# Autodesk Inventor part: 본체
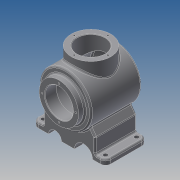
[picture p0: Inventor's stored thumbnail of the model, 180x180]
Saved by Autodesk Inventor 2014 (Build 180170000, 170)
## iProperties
Created: 2018-08
Part Number: 본체
Material: Generic
Document SubType Name: Modeling
Designer: kb542
Density: 1 g/cm^3
Appearance: Default
Author: kb542
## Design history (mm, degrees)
sketch "스케치1"
  geometry: L1 (-60, 0)-(60, 0); L2 (-60, 27)-(-60, 38); L3 (-60, 38)-(-48, 38); L4 (-48, 38)-(-48, 50); L5 (-60, 27)-(-38, 27); L6 (-38, 27)-(-38, 40); L7 (-38, 40)-(42.163, 40); L8 (-48, 50)-(48.671, 50); A1 r 116 centre (-56, 0) between (60, 0) and (48.671, 50); A2 r 106 centre (-56, 0) between (50, 0) and (42.163, 40); 2 further points
  constraints: 16 end point, 4 perpendicular, 4 point on circle, 2 centre point, 2 parallel, 1 coincident, 1 concentric, 1 horizontal, 1 horizontal alignment, 1 midpoint, 1 point on line, 1 vertical alignment
  dimensions: "d0" = 10 radial gap between concentric circles of A1 A2; "d2" = 12 distance of L2.end L3.end; "d4" = 54 diameter of L5 L1; "d5" = 76 diameter of L3 L1; "d6" = 80 diameter of L7 L1; "d7" = 100 diameter of L8 L1; "d8" = 116 radius of A1; "d9" = 22 distance of L2.start L5.end; "d10" = 108 distance from line of L1.end L4
revolve "회전1" sketch "스케치1" stored, may be unused: angle "d11" = 90 deg
node "작업 평면1"
sketch "스케치3"
  geometry: L1 (-50, -43.437)-(-50, -72); L2 (-50, -72)-(-70, -72); L3 (-70, -72)-(-70, -82); L4 (0, 0)-(0, -82); L5 (-70, -82)-(0, -82); L6 (70, -82)-(0, -82); L7 (50, -72)-(70, -72); L8 (70, -72)-(70, -82); L9 (-70, -72)-(-50, -43.437); L10 (70, -72)-(50, -43.437); L11 (50, -43.437)-(50, -72); L12 (-50, -43.437)-(-40.304, -29.59); L13 (50, -43.437)-(40.304, -29.59); C1 r 17.5 at (27.5, -82); C2 r 12.5 at (-27.5, -82); A1 r 50 centre (0, 0) between (-40.304, -29.59) and (40.304, -29.59); 1 further point
  constraints: 26 end point, 5 symmetric about line, 3 centre point, 3 perpendicular, 2 point on circle, 2 point on line, 1 parallel, 1 vertical, 3 other
  dimensions: "d14" = 20 distance between parallel lines of L3 L1; "d15" = 35 diameter of C1; "d16" = 25 diameter of C2; "d17" = 27.5 distance of C2.centre L4.end; "d18" = 27.5 distance of C1.centre L4.end; "d19" = 82 distance from line of L6 point (0, 0); "d21" = 10 distance between parallel lines of L6 L7; "d22" = 140 distance between parallel lines of L8 L3; "d25" = 35 deg angle of L3 L12; "d26" = 35 deg angle of L3 L9
extrude "돌출1" join sketch "스케치3" distance "d27" = 80; taper "d28" = 0 deg
extrude "돌출2" cut sketch "스케치3" stored distance "d29" = 80; taper "d30" = 0 deg
node "작업 평면2"
sketch "스케치4"
  geometry: L1 (-100, 32)-(-100, 108) reference; C1 r 38 at (-38, 70); 1 further point
  constraints: 1 centre point, 1 horizontal alignment
  dimensions: "d32" = 62 distance from line of C1.centre L1; "d33" = 76 diameter of C1
extrude "돌출3" join sketch "스케치4" stored distance "d34" = 80; taper "d35" = 0 deg
sketch "스케치5"
  geometry: C1 r 38 at (0, 0) reference; C2 r 27 at (0, 0); 1 further point
  constraints: 1 centre point, 1 coincident
  dimensions: "d36" = 54 diameter of C2
extrude "돌출4" cut sketch "스케치5" stored distance "d37" = 80; taper "d38" = 0 deg
sketch "스케치6"
  geometry: C1 r 27 at (0, 0) reference; 2 further points
  constraints: 1 horizontal alignment
  dimensions: "d39" = 32.5 distance of C1.centre point (-32.5, 0)
hole "구멍1" sketch "스케치6" at (-32.5, 0) diameter "d40" = 3.242; stored, may be unused: countersink angle "d44" = 90 deg, drill point angle "d46" = 118 deg; dims "d41" = 8, "d42" = 4, "d43" = 2, "d45" = 10
sketch "스케치7"
  geometry: C1 r 38 at (0, 0) reference; 1 further point
  constraints: 1 vertical alignment
  dimensions: "d50" = 32.5 distance of C1.centre point (0, 32.5)
hole "구멍2" sketch "스케치7" at (0, 32.5) diameter "d51" = 3.242; stored, may be unused: countersink angle "d55" = 90 deg, drill point angle "d57" = 118 deg; dims "d52" = 8, "d53" = 4, "d54" = 2, "d56" = 10
fillet "모깎기1" dims "d61" = 10
sketch "스케치8"
  geometry: L1 (70, -120)-(10, -120) reference; L2 (80, -110)-(80, -100) reference; L3 (80, -100)-(0, -100) reference; L4 (0, -110)-(0, -100) reference; A1 r 10 centre (10, 10) between (10, 20) and (0, 10) reference; A2 r 10 centre (70, 10) between (80, 10) and (70, 20) reference; A3 r 10 centre (10, -110) between (0, -110) and (10, -120) reference; A4 r 10 centre (70, -110) between (70, -120) and (80, -110) reference; 5 further points
  constraints: 4 coincident
hole "구멍3" sketch "스케치8" at (10, 10), (70, 10), (70, -110), (10, -110) diameter "d62" = 8; stored, may be unused: countersink angle "d66" = 90 deg, drill point angle "d68" = 118 deg; dims "d63" = 8, "d64" = 4, "d65" = 2, "d67" = 10
node "작업 평면3"
sketch "스케치9"
  geometry: C1 r 32.5 at (0, 0); 1 further point
  constraints: 1 centre point, 1 coincident, 1 other
  dimensions: "d69" = 65 diameter of C1
feature "엠보싱1" sketch "스케치9" dims "d0" = 10, "d2" = 12, "d4" = 54, "d5" = 76, "d6" = 80, "d7" = 100, "d8" = 116, "d9" = 22, "d10" = 108, "d70" = 0.5, "d71" = 0
fillet "모깎기2" dims "d72" = 3
fillet "모깎기3" dims "d73" = 3
fillet "모깎기4" dims "d74" = 3
fillet "모깎기5" dims "d75" = 3
fillet "모깎기6" dims "d76" = 3
chamfer "모따기1" distance "d77" = 1; stored, may be unused: second distance "d78" = 2, angle "d79" = 45 deg
fillet "모깎기7" dims "d80" = 3
node "솔리드1"
pattern_circular "원형 패턴1" dims angle "d48" = 360 deg
pattern_circular "원형 패턴2" dims angle "d59" = 360 deg
node "투영된 루프1"
other parameters: "d12" = -8, "d31" = -147
